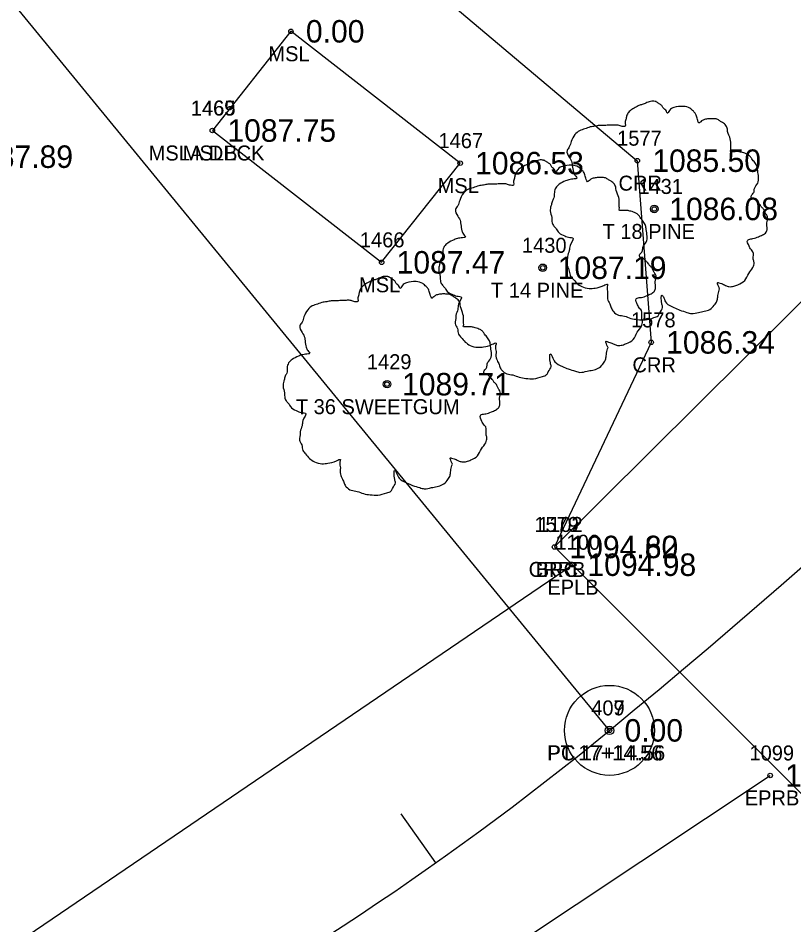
# Model space of a CAD drawing. Extents: x 1539151 to 1541799, y 1198646 to 1201165.
# Drawn here: x 1540056.1 to 1540107.9, y 1199420.8 to 1199481.2 of the extents above; entities that cross this region are included whole.
import ezdxf

# ---------------------------------------------------------------- set-up
doc = ezdxf.new("R2010")
doc.units = 0
for name, color, linetype in [('RD_EX_Bridge', 7, 'Continuous'), ('RD_EX_Bridge_txCode', 7, 'Continuous'), ('RD_EX_H2O', 7, 'Continuous'), ('RD_EX_H2O_txCode', 7, 'Continuous'), ('RD_EX_Misc', 7, 'Continuous'), ('RD_EX_Misc_txCode', 7, 'Continuous'), ('RD_EX_Road', 7, 'Continuous'), ('RD_EX_Road_txCode', 7, 'Continuous'), ('RD_EX_TX_Bridge_ELEV', 7, 'Continuous'), ('RD_EX_TX_Driveway_ELEV', 7, 'Continuous'), ('RD_EX_TX_H2O_ELEV', 7, 'Continuous'), ('RD_EX_TX_Misc_ELEV', 7, 'Continuous'), ('RD_EX_TX_Road_ELEV', 7, 'Continuous'), ('RD_EX_TX_VEG_ELEV', 7, 'Continuous'), ('RD_EX_VEG', 7, 'Continuous'), ('RD_EX_VEG_txCode', 7, 'Continuous'), ('RD_HC_Cl', 7, 'Continuous'), ('RD_HC_Data', 7, 'Continuous'), ('RD_HC_Data_Tic', 7, 'Continuous'), ('RD_HC_Survey_ELEV', 7, 'Continuous'), ('RD_HC_txCode', 7, 'Continuous'), ('RD_SMD_Locator', 7, 'Continuous')]:
    doc.layers.add(name, color=color, linetype=linetype)

msp = doc.modelspace()

# ---------------------------------------------------------------- linework, layer by layer
at = {"layer": 'RD_EX_Bridge'}
msp.add_lwpolyline([(1540110.321, 1199427.558), (1540091.918, 1199445.966), (1540155.709, 1199509.347), (1540174.365, 1199491.069), (1540110.321, 1199427.558)], dxfattribs=at)
at = {"layer": 'RD_EX_H2O'}
msp.add_lwpolyline([(1540037.308, 1199517.449), (1540053.653, 1199500.449), (1540082.887, 1199484.004), (1540097.44, 1199471.738), (1540098.367, 1199459.616), (1540091.918, 1199445.966)], dxfattribs=at)
at = {"layer": 'RD_EX_Misc'}
msp.add_lwpolyline([(1540069.101, 1199473.75), (1540080.387, 1199464.956), (1540085.624, 1199471.574), (1540074.338, 1199480.369), (1540069.101, 1199473.75)], dxfattribs=at)
at = {"layer": 'RD_EX_Road'}
for points in [[(1539428.757, 1199454.927), (1539416.459, 1199395.233), (1539420.912, 1199377.836), (1539428.293, 1199368.53), (1539440.235, 1199363.056), (1539462.842, 1199364.106), (1539506.115, 1199366.587), (1539554.027, 1199368.02), (1539606.532, 1199370.48), (1539651.89, 1199372.758), (1539672.937, 1199372.907), (1539707.025, 1199374.85), (1539748.703, 1199377.616), (1539769.046, 1199378.187), (1539812.936, 1199380.165), (1539830.483, 1199381.226), (1539857.012, 1199382.867), (1539908.221, 1199385.45), (1539955.818, 1199389.743), (1539996.128, 1199397.4), (1540037.848, 1199410.506), (1540050.258, 1199415.612), (1540093.118, 1199444.781)], [(1539925.858, 1199367.851), (1539963.348, 1199372.525), (1539983.912, 1199375.759), (1540009.012, 1199381.588), (1540058.793, 1199399.116), (1540106.307, 1199430.722)]]:
    msp.add_lwpolyline(points, dxfattribs=at)
at = {"layer": 'RD_EX_VEG'}
for centre, radius in [((1540098.572, 1199468.517), 0.25), ((1540098.56, 1199468.498), 0.0001), ((1540091.134, 1199464.593), 0.25), ((1540091.122, 1199464.574), 0.0001), ((1540080.751, 1199456.825), 0.25), ((1540080.738, 1199456.806), 0.0001)]:
    msp.add_circle(centre, radius, dxfattribs=at)
for points in [[(1540098.704, 1199475.684), (1540098.404, 1199475.709), (1540098.08, 1199475.609), (1540097.83, 1199475.509), (1540097.605, 1199475.434), (1540097.38, 1199475.334), (1540097.08, 1199475.159), (1540096.855, 1199474.959), (1540096.73, 1199474.709), (1540096.68, 1199474.485), (1540096.63, 1199474.21), (1540096.63, 1199474.035), (1540096.505, 1199474.01), (1540096.355, 1199474.035), (1540096.105, 1199474.11), (1540095.855, 1199474.11), (1540095.606, 1199474.11), (1540095.256, 1199474.085), (1540094.906, 1199474.085), (1540094.631, 1199474.035), (1540094.306, 1199473.985), (1540093.931, 1199473.86), (1540093.581, 1199473.735), (1540093.282, 1199473.485), (1540093.032, 1199473.01), (1540092.907, 1199472.66), (1540092.757, 1199472.41), (1540092.907, 1199471.961), (1540093.082, 1199471.611), (1540093.107, 1199471.411), (1540093.182, 1199470.986), (1540093.282, 1199470.761), (1540093.407, 1199470.561), (1540093.332, 1199470.536), (1540092.957, 1199470.486), (1540092.657, 1199470.386), (1540092.232, 1199470.161), (1540092.007, 1199469.937), (1540091.907, 1199469.612), (1540091.882, 1199469.262), (1540091.782, 1199469.062), (1540091.707, 1199468.787), (1540091.682, 1199468.712), (1540091.632, 1199468.387), (1540091.732, 1199467.937), (1540091.757, 1199467.588), (1540091.882, 1199467.363), (1540092.032, 1199467.188), (1540092.207, 1199466.938), (1540092.607, 1199466.713), (1540092.932, 1199466.613), (1540093.132, 1199466.588), (1540092.957, 1199466.088), (1540092.907, 1199465.738), (1540092.782, 1199465.339), (1540092.782, 1199465.264), (1540092.732, 1199464.789), (1540092.882, 1199464.464), (1540092.957, 1199464.089), (1540093.132, 1199463.864), (1540093.407, 1199463.564), (1540093.731, 1199463.339), (1540094.231, 1199463.214), (1540094.631, 1199463.239), (1540095.206, 1199463.414), (1540095.456, 1199463.489), (1540095.431, 1199463.314), (1540095.456, 1199462.94), (1540095.456, 1199462.515), (1540095.606, 1199462.19), (1540095.706, 1199461.915), (1540095.855, 1199461.665), (1540096.18, 1199461.44), (1540096.58, 1199461.365), (1540097.005, 1199461.215), (1540097.455, 1199461.14), (1540097.955, 1199461.115), (1540098.554, 1199461.265), (1540098.829, 1199461.39), (1540098.929, 1199461.565), (1540099.129, 1199461.94), (1540099.079, 1199462.165), (1540099.104, 1199462.765), (1540099.204, 1199462.59), (1540099.379, 1199462.24), (1540099.879, 1199461.94), (1540100.279, 1199461.765), (1540100.753, 1199461.615), (1540101.053, 1199461.54), (1540101.528, 1199461.615), (1540101.903, 1199461.69), (1540102.278, 1199461.815), (1540102.578, 1199462.09), (1540102.752, 1199462.365), (1540102.802, 1199462.64), (1540102.877, 1199463.015), (1540102.927, 1199463.189)], [(1540102.927, 1199463.189), (1540102.852, 1199463.364), (1540102.802, 1199463.614), (1540102.877, 1199463.589), (1540103.052, 1199463.539), (1540103.327, 1199463.414), (1540103.552, 1199463.339), (1540103.877, 1199463.364), (1540104.152, 1199463.464), (1540104.602, 1199463.739), (1540104.877, 1199464.214), (1540105.151, 1199464.614), (1540105.226, 1199464.939), (1540105.176, 1199465.164), (1540105.151, 1199465.663), (1540104.951, 1199465.913), (1540104.901, 1199466.038), (1540104.802, 1199466.438), (1540104.877, 1199466.488), (1540105.151, 1199466.538), (1540105.526, 1199466.663), (1540105.801, 1199466.788), (1540106.026, 1199466.963), (1540106.101, 1199467.188), (1540106.076, 1199467.588), (1540106.126, 1199467.987), (1540106.051, 1199468.137), (1540105.951, 1199468.287), (1540105.876, 1199468.487), (1540105.726, 1199468.637), (1540105.626, 1199468.787), (1540105.526, 1199468.887), (1540105.401, 1199469.037), (1540105.226, 1199469.162), (1540105.076, 1199469.212), (1540105.026, 1199469.362), (1540105.176, 1199469.562), (1540105.226, 1199469.662), (1540105.251, 1199469.887), (1540105.476, 1199470.236), (1540105.526, 1199470.636), (1540105.476, 1199471.061), (1540105.426, 1199471.336), (1540105.276, 1199471.611), (1540105.076, 1199471.861), (1540104.951, 1199472.036), (1540104.777, 1199472.161), (1540104.452, 1199472.286), (1540104.202, 1199472.335), (1540103.852, 1199472.335), (1540103.652, 1199472.385), (1540103.677, 1199472.435), (1540103.677, 1199472.585), (1540103.677, 1199472.86), (1540103.602, 1199473.31), (1540103.452, 1199473.81), (1540103.452, 1199473.835), (1540103.352, 1199474.085), (1540103.127, 1199474.285), (1540102.952, 1199474.385), (1540102.752, 1199474.51), (1540102.503, 1199474.535), (1540102.203, 1199474.535), (1540101.928, 1199474.485), (1540101.728, 1199474.385), (1540101.553, 1199474.26), (1540101.478, 1199474.41), (1540101.378, 1199474.709), (1540101.328, 1199474.859), (1540101.178, 1199475.034), (1540100.953, 1199475.234), (1540100.503, 1199475.359), (1540099.879, 1199475.284), (1540099.579, 1199475.084), (1540099.429, 1199474.909), (1540099.379, 1199475.034), (1540099.179, 1199475.234), (1540099.079, 1199475.409), (1540098.904, 1199475.534), (1540098.754, 1199475.634), (1540098.654, 1199475.684)], [(1540091.266, 1199471.76), (1540090.966, 1199471.785), (1540090.641, 1199471.685), (1540090.392, 1199471.585), (1540090.167, 1199471.51), (1540089.942, 1199471.41), (1540089.642, 1199471.235), (1540089.417, 1199471.035), (1540089.292, 1199470.785), (1540089.242, 1199470.56), (1540089.192, 1199470.286), (1540089.192, 1199470.111), (1540089.067, 1199470.086), (1540088.917, 1199470.111), (1540088.667, 1199470.186), (1540088.417, 1199470.186), (1540088.167, 1199470.186), (1540087.818, 1199470.161), (1540087.468, 1199470.161), (1540087.193, 1199470.111), (1540086.868, 1199470.061), (1540086.493, 1199469.936), (1540086.143, 1199469.811), (1540085.844, 1199469.561), (1540085.594, 1199469.086), (1540085.469, 1199468.736), (1540085.319, 1199468.486), (1540085.469, 1199468.037), (1540085.644, 1199467.687), (1540085.669, 1199467.487), (1540085.744, 1199467.062), (1540085.844, 1199466.837), (1540085.968, 1199466.637), (1540085.894, 1199466.612), (1540085.519, 1199466.562), (1540085.219, 1199466.462), (1540084.794, 1199466.237), (1540084.569, 1199466.012), (1540084.469, 1199465.688), (1540084.444, 1199465.338), (1540084.344, 1199465.138), (1540084.269, 1199464.863), (1540084.244, 1199464.788), (1540084.194, 1199464.463), (1540084.294, 1199464.013), (1540084.319, 1199463.663), (1540084.444, 1199463.439), (1540084.594, 1199463.264), (1540084.769, 1199463.014), (1540085.169, 1199462.789), (1540085.494, 1199462.689), (1540085.694, 1199462.664), (1540085.519, 1199462.164), (1540085.469, 1199461.814), (1540085.344, 1199461.414), (1540085.344, 1199461.34), (1540085.294, 1199460.865), (1540085.444, 1199460.54), (1540085.519, 1199460.165), (1540085.694, 1199459.94), (1540085.968, 1199459.64), (1540086.293, 1199459.415), (1540086.793, 1199459.29), (1540087.193, 1199459.315), (1540087.768, 1199459.49), (1540088.018, 1199459.565), (1540087.993, 1199459.39), (1540088.018, 1199459.015), (1540088.018, 1199458.591), (1540088.167, 1199458.266), (1540088.267, 1199457.991), (1540088.417, 1199457.741), (1540088.742, 1199457.516), (1540089.142, 1199457.441), (1540089.567, 1199457.291), (1540090.017, 1199457.216), (1540090.516, 1199457.191), (1540091.116, 1199457.341), (1540091.391, 1199457.466), (1540091.491, 1199457.641), (1540091.691, 1199458.016), (1540091.641, 1199458.241), (1540091.666, 1199458.841), (1540091.766, 1199458.666), (1540091.941, 1199458.316), (1540092.441, 1199458.016), (1540092.84, 1199457.841), (1540093.315, 1199457.691), (1540093.615, 1199457.616), (1540094.09, 1199457.691), (1540094.465, 1199457.766), (1540094.84, 1199457.891), (1540095.139, 1199458.166), (1540095.314, 1199458.441), (1540095.364, 1199458.716), (1540095.439, 1199459.09), (1540095.489, 1199459.265)], [(1540095.489, 1199459.265), (1540095.414, 1199459.44), (1540095.364, 1199459.69), (1540095.439, 1199459.665), (1540095.614, 1199459.615), (1540095.889, 1199459.49), (1540096.114, 1199459.415), (1540096.439, 1199459.44), (1540096.714, 1199459.54), (1540097.164, 1199459.815), (1540097.438, 1199460.29), (1540097.713, 1199460.69), (1540097.788, 1199461.015), (1540097.738, 1199461.24), (1540097.713, 1199461.739), (1540097.513, 1199461.989), (1540097.463, 1199462.114), (1540097.363, 1199462.514), (1540097.438, 1199462.564), (1540097.713, 1199462.614), (1540098.088, 1199462.739), (1540098.363, 1199462.864), (1540098.588, 1199463.039), (1540098.663, 1199463.264), (1540098.638, 1199463.663), (1540098.688, 1199464.063), (1540098.613, 1199464.213), (1540098.513, 1199464.363), (1540098.438, 1199464.563), (1540098.288, 1199464.713), (1540098.188, 1199464.863), (1540098.088, 1199464.963), (1540097.963, 1199465.113), (1540097.788, 1199465.238), (1540097.638, 1199465.288), (1540097.588, 1199465.438), (1540097.738, 1199465.638), (1540097.788, 1199465.738), (1540097.813, 1199465.962), (1540098.038, 1199466.312), (1540098.088, 1199466.712), (1540098.038, 1199467.137), (1540097.988, 1199467.412), (1540097.838, 1199467.687), (1540097.638, 1199467.937), (1540097.513, 1199468.112), (1540097.338, 1199468.236), (1540097.014, 1199468.361), (1540096.764, 1199468.411), (1540096.414, 1199468.411), (1540096.214, 1199468.461), (1540096.239, 1199468.511), (1540096.239, 1199468.661), (1540096.239, 1199468.936), (1540096.164, 1199469.386), (1540096.014, 1199469.886), (1540096.014, 1199469.911), (1540095.914, 1199470.161), (1540095.689, 1199470.361), (1540095.514, 1199470.46), (1540095.314, 1199470.585), (1540095.064, 1199470.61), (1540094.765, 1199470.61), (1540094.49, 1199470.56), (1540094.29, 1199470.46), (1540094.115, 1199470.336), (1540094.04, 1199470.485), (1540093.94, 1199470.785), (1540093.89, 1199470.935), (1540093.74, 1199471.11), (1540093.515, 1199471.31), (1540093.065, 1199471.435), (1540092.441, 1199471.36), (1540092.141, 1199471.16), (1540091.991, 1199470.985), (1540091.941, 1199471.11), (1540091.741, 1199471.31), (1540091.641, 1199471.485), (1540091.466, 1199471.61), (1540091.316, 1199471.71), (1540091.216, 1199471.76)], [(1540080.883, 1199463.992), (1540080.583, 1199464.017), (1540080.258, 1199463.917), (1540080.008, 1199463.817), (1540079.783, 1199463.742), (1540079.559, 1199463.642), (1540079.259, 1199463.467), (1540079.034, 1199463.267), (1540078.909, 1199463.017), (1540078.859, 1199462.792), (1540078.809, 1199462.518), (1540078.809, 1199462.343), (1540078.684, 1199462.318), (1540078.534, 1199462.343), (1540078.284, 1199462.418), (1540078.034, 1199462.418), (1540077.784, 1199462.418), (1540077.434, 1199462.393), (1540077.085, 1199462.393), (1540076.81, 1199462.343), (1540076.485, 1199462.293), (1540076.11, 1199462.168), (1540075.76, 1199462.043), (1540075.46, 1199461.793), (1540075.21, 1199461.318), (1540075.085, 1199460.968), (1540074.936, 1199460.718), (1540075.085, 1199460.269), (1540075.26, 1199459.919), (1540075.285, 1199459.719), (1540075.36, 1199459.294), (1540075.46, 1199459.069), (1540075.585, 1199458.869), (1540075.51, 1199458.844), (1540075.135, 1199458.794), (1540074.836, 1199458.694), (1540074.411, 1199458.469), (1540074.186, 1199458.244), (1540074.086, 1199457.92), (1540074.061, 1199457.57), (1540073.961, 1199457.37), (1540073.886, 1199457.095), (1540073.861, 1199457.02), (1540073.811, 1199456.695), (1540073.911, 1199456.245), (1540073.936, 1199455.895), (1540074.061, 1199455.671), (1540074.211, 1199455.496), (1540074.386, 1199455.246), (1540074.786, 1199455.021), (1540075.11, 1199454.921), (1540075.31, 1199454.896), (1540075.135, 1199454.396), (1540075.085, 1199454.046), (1540074.961, 1199453.646), (1540074.961, 1199453.572), (1540074.911, 1199453.097), (1540075.06, 1199452.772), (1540075.135, 1199452.397), (1540075.31, 1199452.172), (1540075.585, 1199451.872), (1540075.91, 1199451.647), (1540076.41, 1199451.522), (1540076.81, 1199451.547), (1540077.385, 1199451.722), (1540077.634, 1199451.797), (1540077.609, 1199451.622), (1540077.634, 1199451.247), (1540077.634, 1199450.823), (1540077.784, 1199450.498), (1540077.884, 1199450.223), (1540078.034, 1199449.973), (1540078.359, 1199449.748), (1540078.759, 1199449.673), (1540079.184, 1199449.523), (1540079.634, 1199449.448), (1540080.133, 1199449.423), (1540080.733, 1199449.573), (1540081.008, 1199449.698), (1540081.108, 1199449.873), (1540081.308, 1199450.248), (1540081.258, 1199450.473), (1540081.283, 1199451.073), (1540081.383, 1199450.898), (1540081.558, 1199450.548), (1540082.057, 1199450.248), (1540082.457, 1199450.073), (1540082.932, 1199449.923), (1540083.232, 1199449.848), (1540083.707, 1199449.923), (1540084.082, 1199449.998), (1540084.456, 1199450.123), (1540084.756, 1199450.398), (1540084.931, 1199450.673), (1540084.981, 1199450.948), (1540085.056, 1199451.322), (1540085.106, 1199451.497)], [(1540085.106, 1199451.497), (1540085.031, 1199451.672), (1540084.981, 1199451.922), (1540085.056, 1199451.897), (1540085.231, 1199451.847), (1540085.506, 1199451.722), (1540085.731, 1199451.647), (1540086.056, 1199451.672), (1540086.331, 1199451.772), (1540086.78, 1199452.047), (1540087.055, 1199452.522), (1540087.33, 1199452.922), (1540087.405, 1199453.247), (1540087.355, 1199453.472), (1540087.33, 1199453.971), (1540087.13, 1199454.221), (1540087.08, 1199454.346), (1540086.98, 1199454.746), (1540087.055, 1199454.796), (1540087.33, 1199454.846), (1540087.705, 1199454.971), (1540087.98, 1199455.096), (1540088.205, 1199455.271), (1540088.28, 1199455.496), (1540088.255, 1199455.895), (1540088.305, 1199456.295), (1540088.23, 1199456.445), (1540088.13, 1199456.595), (1540088.055, 1199456.795), (1540087.905, 1199456.945), (1540087.805, 1199457.095), (1540087.705, 1199457.195), (1540087.58, 1199457.345), (1540087.405, 1199457.47), (1540087.255, 1199457.52), (1540087.205, 1199457.67), (1540087.355, 1199457.87), (1540087.405, 1199457.97), (1540087.43, 1199458.194), (1540087.655, 1199458.544), (1540087.705, 1199458.944), (1540087.655, 1199459.369), (1540087.605, 1199459.644), (1540087.455, 1199459.919), (1540087.255, 1199460.169), (1540087.13, 1199460.344), (1540086.955, 1199460.468), (1540086.63, 1199460.593), (1540086.381, 1199460.643), (1540086.031, 1199460.643), (1540085.831, 1199460.693), (1540085.856, 1199460.743), (1540085.856, 1199460.893), (1540085.856, 1199461.168), (1540085.781, 1199461.618), (1540085.631, 1199462.118), (1540085.631, 1199462.143), (1540085.531, 1199462.393), (1540085.306, 1199462.593), (1540085.131, 1199462.692), (1540084.931, 1199462.817), (1540084.681, 1199462.842), (1540084.381, 1199462.842), (1540084.107, 1199462.792), (1540083.907, 1199462.692), (1540083.732, 1199462.568), (1540083.657, 1199462.717), (1540083.557, 1199463.017), (1540083.507, 1199463.167), (1540083.357, 1199463.342), (1540083.132, 1199463.542), (1540082.682, 1199463.667), (1540082.057, 1199463.592), (1540081.758, 1199463.392), (1540081.608, 1199463.217), (1540081.558, 1199463.342), (1540081.358, 1199463.542), (1540081.258, 1199463.717), (1540081.083, 1199463.842), (1540080.933, 1199463.942), (1540080.833, 1199463.992)]]:
    msp.add_spline(points, degree=3, dxfattribs=at)
at = {"layer": 'RD_HC_Cl'}
for centre, radius, start, end in [((1539789.523, 1199807.077), 482.768, 309.34428, 325.59235), ((1539965.208, 1199592.77), 205.654, 284.82206, 309.34428)]:
    msp.add_arc(centre, radius, start, end, dxfattribs=at)
at = {"layer": 'RD_HC_Data'}
msp.add_line((1540095.588, 1199433.728), (1540017.726, 1199528.706), dxfattribs=at)
for radius in [3, 3, 0.282, 0.282]:
    msp.add_circle((1540095.588, 1199433.728), radius, dxfattribs=at)
at = {"layer": 'RD_HC_Data_Tic'}
msp.add_line((1540084.009, 1199424.902), (1540081.699, 1199428.167), dxfattribs=at)
at = {"layer": 'RD_SMD_Locator'}
for centre in [(1540074.338, 1199480.369), (1540069.101, 1199473.75), (1540069.101, 1199473.75), (1540085.624, 1199471.574), (1540097.44, 1199471.738), (1540098.572, 1199468.517), (1540080.387, 1199464.956), (1540091.134, 1199464.593), (1540098.367, 1199459.616), (1540080.751, 1199456.825), (1540091.918, 1199445.966), (1540091.918, 1199445.966), (1540093.118, 1199444.781), (1540095.588, 1199433.728), (1540095.588, 1199433.728), (1540106.307, 1199430.722)]:
    msp.add_circle(centre, 0.15, dxfattribs=at)

# ---------------------------------------------------------------- texts
at = {"layer": 'RD_EX_Bridge_txCode'}
for s, p in [('1102', (1540090.816, 1199446.966)), ('BRC', (1540090.666, 1199443.966))]:
    msp.add_text(s, height=1, dxfattribs=at).set_placement(p)
at = {"layer": 'RD_EX_H2O_txCode'}
for s, p in [('1577', (1540096.094, 1199472.738)), ('CRR', (1540096.188, 1199469.738)), ('1578', (1540097.02, 1199460.616)), ('CRR', (1540097.115, 1199457.616)), ('1579', (1540090.572, 1199446.966)), ('CRRB', (1540090.194, 1199443.966))]:
    msp.add_text(s, height=1, dxfattribs=at).set_placement(p)
at = {"layer": 'RD_EX_Misc_txCode'}
for s, p in [('MSL', (1540072.835, 1199478.369)), ('1469', (1540067.655, 1199474.75)), ('1465', (1540067.672, 1199474.75)), ('1467', (1540084.18, 1199472.574)), ('MSLA DECK', (1540064.849, 1199471.75)), ('MSLB', (1540067.13, 1199471.75)), ('MSL', (1540084.122, 1199469.574)), ('1466', (1540078.938, 1199465.956)), ('MSL', (1540078.885, 1199462.956))]:
    msp.add_text(s, height=1, dxfattribs=at).set_placement(p)
at = {"layer": 'RD_EX_Road_txCode'}
for s, p in [('1100', (1540091.977, 1199445.781)), ('EPLB', (1540091.441, 1199442.781)), ('1099', (1540104.921, 1199431.722)), ('EPRB', (1540104.607, 1199428.722))]:
    msp.add_text(s, height=1, dxfattribs=at).set_placement(p)
at = {"layer": 'RD_EX_TX_Bridge_ELEV'}
msp.add_text('1094.82', height=1.5, dxfattribs=at).set_placement((1540092.918, 1199445.216))
at = {"layer": 'RD_EX_TX_Driveway_ELEV'}
msp.add_text('1087.89', height=1.5, dxfattribs=at).set_placement((1540052.556, 1199471.255))
at = {"layer": 'RD_EX_TX_H2O_ELEV'}
for s, p in [('1085.50', (1540098.44, 1199470.988)), ('1086.34', (1540099.367, 1199458.866)), ('1094.60', (1540092.918, 1199445.216))]:
    msp.add_text(s, height=1.5, dxfattribs=at).set_placement(p)
at = {"layer": 'RD_EX_TX_Misc_ELEV'}
for s, p in [('0.00', (1540075.338, 1199479.619)), ('1087.75', (1540070.101, 1199473)), ('1087.75', (1540070.101, 1199473)), ('1086.53', (1540086.624, 1199470.824)), ('1087.47', (1540081.387, 1199464.206))]:
    msp.add_text(s, height=1.5, dxfattribs=at).set_placement(p)
at = {"layer": 'RD_EX_TX_Road_ELEV'}
for s, p in [('1094.98', (1540094.118, 1199444.031)), ('1095.09', (1540107.307, 1199429.972))]:
    msp.add_text(s, height=1.5, dxfattribs=at).set_placement(p)
at = {"layer": 'RD_EX_TX_VEG_ELEV'}
for s, p in [('1086.08', (1540099.572, 1199467.767)), ('1087.19', (1540092.134, 1199463.843)), ('1089.71', (1540081.751, 1199456.075))]:
    msp.add_text(s, height=1.5, dxfattribs=at).set_placement(p)
at = {"layer": 'RD_EX_VEG_txCode'}
for s, p in [('1431', (1540097.509, 1199469.517)), ('T 18 PINE', (1540095.12, 1199466.517)), ('1430', (1540089.748, 1199465.593)), ('T 14 PINE', (1540087.681, 1199462.593)), ('1429', (1540079.405, 1199457.825)), ('T 36 SWEETGUM', (1540074.664, 1199454.825))]:
    msp.add_text(s, height=1, dxfattribs=at).set_placement(p)
at = {"layer": 'RD_HC_Data'}
msp.add_text('S 38%%d 22\' 03" E', height=6, rotation=308.36748, dxfattribs=at).set_placement((1540096.163, 1199509.93))
at = {"layer": 'RD_HC_Survey_ELEV'}
msp.add_text('0.00', height=1.5, dxfattribs=at).set_placement((1540096.588, 1199432.978))
msp.add_text('0.00', height=1.5, dxfattribs=at).set_placement((1540096.588, 1199432.978))
at = {"layer": 'RD_HC_txCode'}
for s, p in [('407', (1540094.367, 1199434.728)), ('409', (1540094.367, 1199434.728)), ('PT 17+14.56', (1540091.423, 1199431.728)), ('PC 17+14.56', (1540091.454, 1199431.728))]:
    msp.add_text(s, height=1, dxfattribs=at).set_placement(p)

doc.saveas('drawing.dxf')
